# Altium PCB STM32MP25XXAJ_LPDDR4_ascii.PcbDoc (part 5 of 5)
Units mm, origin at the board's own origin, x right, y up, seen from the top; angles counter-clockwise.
Board outline 172 x 137 mm, 4 copper layers (Top Layer, Signal Layer 1, Signal Layer 2, Bottom Layer), stack 1.614 mm thick; 188 components, 294 nets, 1141 pads, 872 vias.
Unrouted connection lines stored in the file: 13.
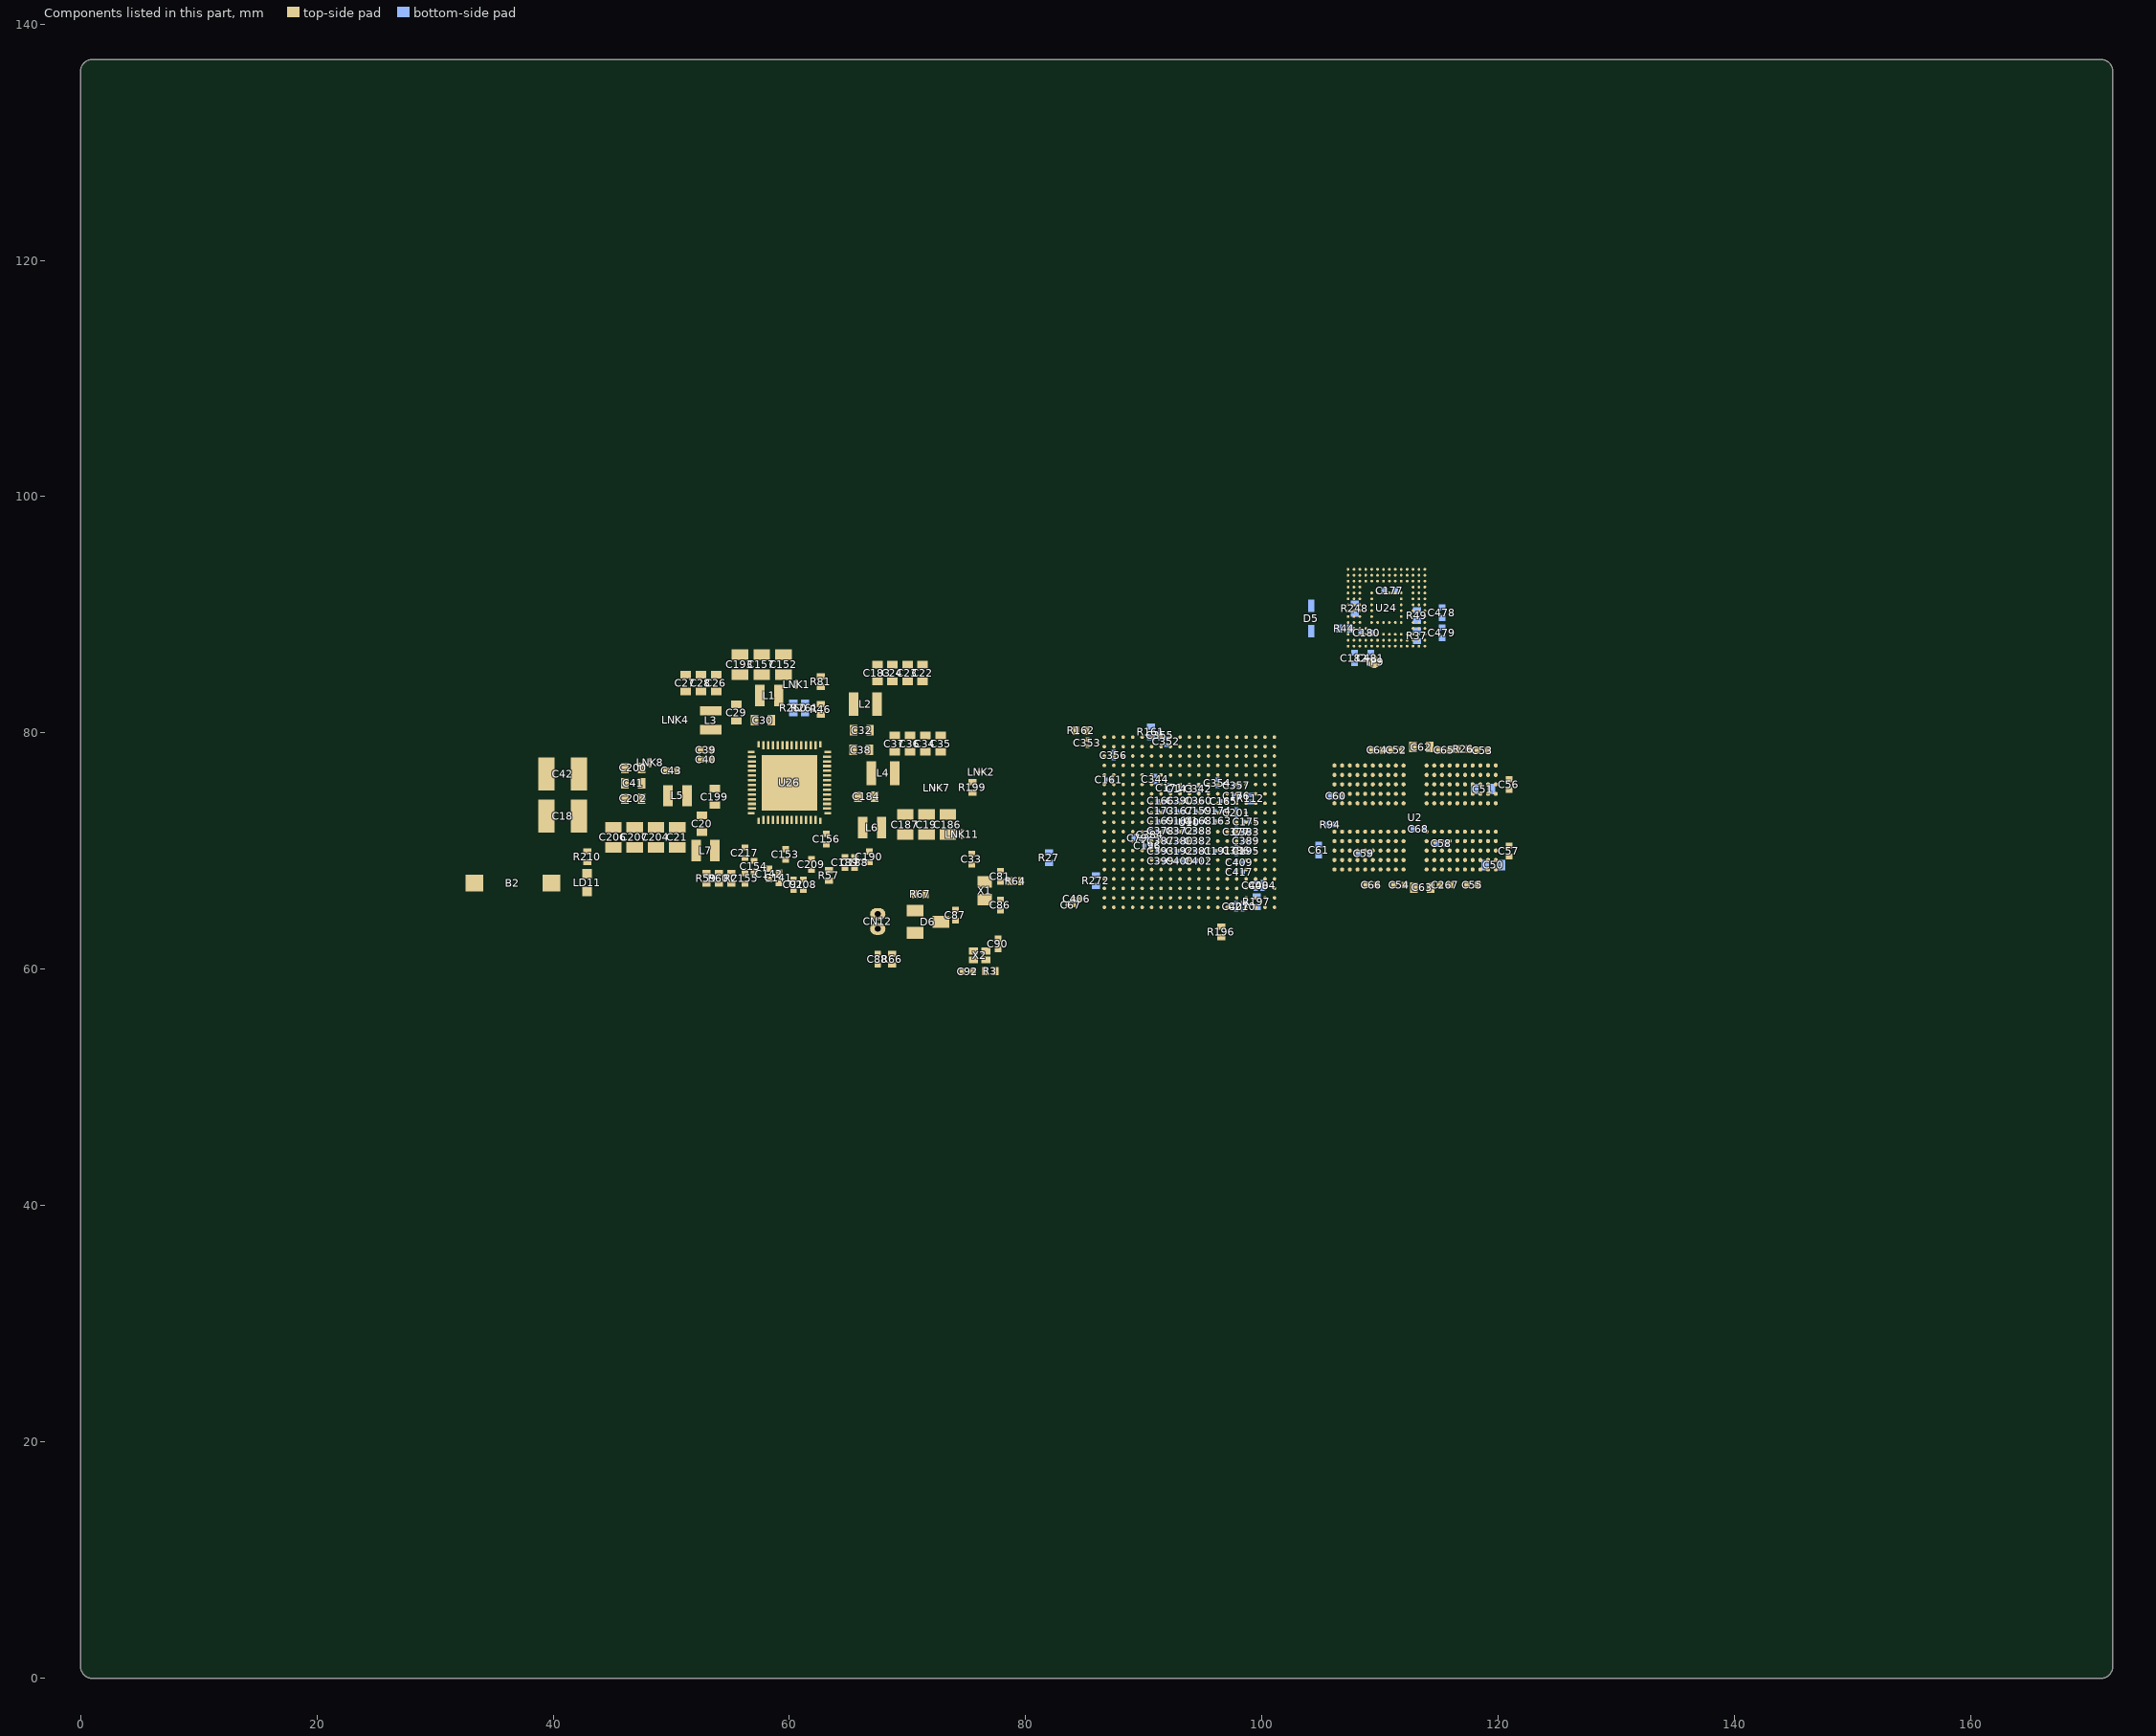
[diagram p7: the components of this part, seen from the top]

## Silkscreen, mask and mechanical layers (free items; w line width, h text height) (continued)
Drill Drawing:
  drawing of 183 lines, arcs and shapes, not listed
  text "PCB SPECIFICATIONS :" at 3.455,183.85 h3
  text "MINIMUN PARAMETERS" at 155.325,183.145 h3
  text "PCB : TYPE 3" at 194.663,183.121 h3
  text "A.   MATERIAL :" at 3.455,179.85 h3
  text "FR-4" at 41.955,179.85 h3
  text "TG-170" at 58.455,179.85 h3
  text "X  TG-150" at 76.705,179.85 h3
  text "TG-140" at 92.705,179.85 h3
  text "DEFAULT" at 155.325,177.645 h3
  text "ASPECT-RATIO, AXE Z :" at 194.663,177.621 h3
  text "B.   MATERIAL FAMILY :" at 3.455,176.85 h3
  text "N/A" at 41.955,176.85 h3
  text "C.   SOLDERMASK COLOR :" at 3.455,173.85 h3
  text "GREEN" at 41.955,173.85 h3
  text "X  BLUE" at 58.455,173.85 h3
  text "RED" at 76.705,173.85 h3
  text "BLACK" at 92.705,173.85 h3
  text "TRACKS : 0.100mm           / GAPS : 0.100mm" at 155.325,171.895 h3
  text "6 :1  to  8 :1 / LEVEL \"B\"" at 194.682,170.874 h3
  text "D.   SILKSCREEN COLOR :" at 3.455,170.85 h3
  text "X  WHITE" at 41.955,170.85 h3
  text "YELLOW" at 58.455,170.85 h3
  text "BLACK" at 76.705,170.85 h3
  text "E.   SURFACE FINISH :" at 3.455,167.85 h3
  text "X  ENIG" at 41.955,167.85 h3
  text "IMMERSION SILVER" at 58.455,167.85 h3
  text "IMMERSION TIN" at 92.705,167.85 h3
  text "BGA :" at 155.3,167.07 h3
  text "Layer" at 244.479,166.45 h2
  text "Name" at 252.853,166.45 h2
  text "Material" at 269.05,166.45 h2
  text "Thickness" at 283.604,166.45 h2
  text "Constant" at 295.559,166.45 h2
  text "HASL" at 41.955,164.85 h3
  text "HASL (PB-FREE)" at 58.455,164.85 h3
  text "GOLDEN FINGER" at 92.705,164.85 h3
  text "Top Overlay" at 252.853,162.45 h2
  text "F.   IMPEDANCE CONTROL :" at 3.455,161.85 h3
  text "NO" at 41.955,161.85 h3
  text "X  YES" at 58.455,161.85 h3
  text "TRACKS : 0.090mm           / GAPS : 0.090mm" at 155.3,161.32 h3
  text "G.   THROUGH VIA :" at 3.455,158.85 h3
  text "PLUG THE VIAS WHICH ARE COVERED WITH SOLDERMASK ONE OR TWO SIDE." at 41.955,158.85 h3
  text "Top Solder" at 252.853,158.45 h2
  text "Solder Resist" at 269.05,158.45 h2
  text "0.025mm" at 283.604,158.45 h2
  text "3.5" at 295.559,158.45 h2
  text "PLUG MATERIAL :" at 41.955,155.85 h3
  text "X  SOLDERMASK" at 67.455,155.85 h3
  text "NON-CONDUCTIVE EPOXY." at 92.705,155.85 h3
  text "1" at 244.479,154.45 h2
  text "Top Layer" at 252.853,154.45 h2
  text "0.037mm" at 283.604,154.45 h2
  text "H.   STACK-UP :" at 3.455,152.85 h3
  text "SEE LAYER STACK-UP SEQUENCE FOR OVERALL THICKNESS." at 41.955,152.85 h3
  text "Dielectric 1" at 252.853,150.45 h2
  text "0.070mm" at 283.604,150.45 h2
  text "3.8" at 295.559,150.45 h2
  text "2" at 244.478,146.45 h2
  text "Signal Layer 1" at 252.853,146.45 h2
  text "0.035mm" at 283.604,146.45 h2
  text "Dielectric 2" at 252.853,142.45 h2
  text "1.330mm" at 283.604,142.45 h2
  text "4.3" at 295.559,142.45 h2
  text "3" at 244.479,138.45 h2
  text "Signal Layer 2" at 252.853,138.45 h2
  text "0.035mm" at 283.604,138.45 h2
  text "Dielectric 3" at 252.853,134.45 h2
  text "0.070mm" at 283.604,134.45 h2
  text "3.8" at 295.559,134.45 h2
  text "4" at 244.479,130.45 h2
  text "Bottom Layer" at 252.853,130.45 h2
  text "0.037mm" at 283.604,130.45 h2
  text "Bottom Solder" at 252.853,126.45 h2
  text "Solder Resist" at 269.05,126.45 h2
  text "0.025mm" at 283.604,126.45 h2
  text "3.5" at 295.559,126.45 h2
  text "Bottom Overlay" at 252.853,122.45 h2
  text "Symbol" at 183.644,16.166 h2.4
  text "Count" at 193.043,16.166 h2.4
  text "Hole Size" at 202.8,16.166 h2.4
  text "Plated" at 221.077,16.166 h2.4
  text "Hole Type" at 229.328,16.166 h2.4
  text "Drill Layer Pair" at 241.34,16.166 h2.4
  text "Via/Pad" at 264.12,16.166 h2.4
  text "Pad Shape" at 273.963,16.166 h2.4
  text "Hole Length" at 286.82,16.166 h2.4
  text "523" at 193.043,12.023 h2
  text "0.200mm (7.87mil)" at 202.8,12.023 h2
  text "PTH" at 221.077,12.023 h2
  text "Round" at 229.328,12.023 h2
  text "Top Layer - Bottom Layer" at 241.34,12.023 h2
  text "Via" at 264.12,12.023 h2
  text "Rounded" at 273.963,12.023 h2
  text "-" at 286.82,12.023 h2
  text "D" at 182.856,11.769 h1.84
  text "349" at 193.043,7.88 h2
  text "0.350mm (13.78mil)" at 202.8,7.88 h2
  text "PTH" at 221.077,7.88 h2
  text "Round" at 229.328,7.88 h2
  text "Top Layer - Bottom Layer" at 241.34,7.88 h2
  text "Via" at 264.12,7.88 h2
  text "Rounded" at 273.963,7.88 h2
  text "-" at 286.82,7.88 h2
  text "F" at 182.856,7.626 h1.84
  text "2" at 193.043,3.737 h2
  text "0.500mm (19.69mil)" at 202.8,3.737 h2
  text "PTH" at 221.077,3.737 h2
  text "Round" at 229.328,3.737 h2
  text "Top Layer - Bottom Layer" at 241.34,3.737 h2
  text "Pad" at 264.12,3.737 h2
  text "Rounded" at 273.963,3.737 h2
  text "-" at 286.82,3.737 h2
  text "874 Total" at 193.043,-0.407 h2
